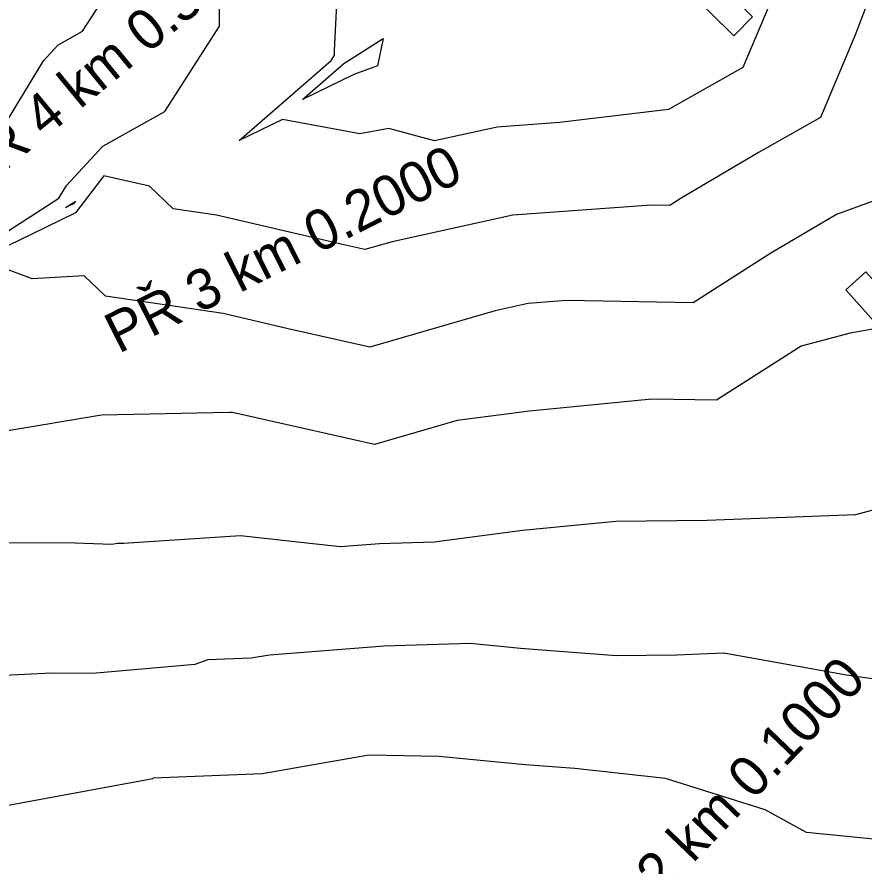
# Model space of a CAD drawing. Extents: x -549394 to -546608, y -1037055 to -1033629.
# Drawn here: x -548001.4 to -547811.8, y -1034975.5 to -1034785.5 of the extents above; entities that cross this region are included whole.
import ezdxf

# ---------------------------------------------------------------- set-up
doc = ezdxf.new("R2010")
doc.units = 0
for name, color, linetype in [('hlavni_vrst', 7, 'Continuous'), ('norm_vrst', 7, 'Continuous'), ('x_popis_oblouky_C21', 7, 'Continuous'), ('x_popis_pricne_rezy_C21', 7, 'Continuous')]:
    doc.layers.add(name, color=color, linetype=linetype)

msp = doc.modelspace()

# ---------------------------------------------------------------- linework, layer by layer
at = {"layer": 'hlavni_vrst'}
for p, q in [((-547930.28, -1034793.03), (-547929.09, -1034769.59)), ((-547831.37, -1034778.88), (-547838.89, -1034796.79)), ((-547930.29, -1034794.03), (-547930.28, -1034793.03)), ((-547931.04, -1034795.2), (-547930.29, -1034794.03)), ((-547951.64, -1034813.16), (-547931.04, -1034795.2)), ((-547838.89, -1034796.79), (-547855.54, -1034806.2)), ((-547855.54, -1034806.2), (-547879.97, -1034809.11)), ((-547941.92, -1034808.45), (-547951.64, -1034813.16)), ((-547924.61, -1034811.63), (-547941.92, -1034808.45)), ((-547893.86, -1034810.13), (-547907.91, -1034813.21)), ((-547879.97, -1034809.11), (-547893.86, -1034810.13)), ((-547918.17, -1034810.42), (-547924.61, -1034811.63)), ((-547907.91, -1034813.21), (-547918.17, -1034810.42)), ((-547990.49, -1034828.14), (-547988.82, -1034827.07)), ((-547988.74, -1034827.29), (-547990.49, -1034828.14)), ((-547988.82, -1034827.07), (-547988.28, -1034826.69)), ((-547988.28, -1034826.69), (-547988.74, -1034827.29)), ((-547899.96, -1034925.75), (-547919.16, -1034926.31)), ((-547888.65, -1034926.85), (-547899.96, -1034925.75)), ((-547919.16, -1034926.31), (-547944.85, -1034928.3)), ((-547867.23, -1034928.45), (-547888.65, -1034926.85)), ((-547843.16, -1034927.89), (-547853.64, -1034928.29)), ((-547815.68, -1034932.82), (-547843.16, -1034927.89)), ((-547958.65, -1034929.4), (-547961.54, -1034930.44)), ((-547948.95, -1034929.01), (-547958.65, -1034929.4)), ((-547944.85, -1034928.3), (-547948.95, -1034929.01)), ((-547853.64, -1034928.29), (-547867.23, -1034928.45)), ((-547961.54, -1034930.44), (-547984.49, -1034932.45)), ((-547993.65, -1034932.39), (-548021.3, -1034933.65)), ((-547984.49, -1034932.45), (-547993.65, -1034932.39)), ((-547782.76, -1034937.38), (-547815.68, -1034932.82))]:
    msp.add_line(p, q, dxfattribs=at)
at = {"layer": 'norm_vrst'}
for p, q in [((-547956.05, -1034787.56), (-547955.75, -1034744.77)), ((-547807.11, -1034772.14), (-547813.87, -1034789.74)), ((-547986.68, -1034788.68), (-547981.82, -1034781.1)), ((-547992.19, -1034791.77), (-547986.68, -1034788.68)), ((-547968.28, -1034806.63), (-547956.05, -1034787.56)), ((-547928.21, -1034795.9), (-547919.44, -1034790.29)), ((-547919.44, -1034790.29), (-547920.65, -1034796.4)), ((-547813.87, -1034789.74), (-547821.53, -1034807.96)), ((-547995.42, -1034795.27), (-547992.19, -1034791.77)), ((-548004.18, -1034809.72), (-547995.42, -1034795.27)), ((-547937.43, -1034803.93), (-547928.21, -1034795.9)), ((-547920.65, -1034796.4), (-547925.94, -1034798.36)), ((-547925.94, -1034798.36), (-547937.43, -1034803.93)), ((-547982.15, -1034814.41), (-547968.28, -1034806.63)), ((-547821.53, -1034807.96), (-547835.25, -1034815.72)), ((-547990.28, -1034823.21), (-547982.15, -1034814.41)), ((-547835.25, -1034815.72), (-547852.72, -1034826.06)), ((-547981.95, -1034821.06), (-547988.27, -1034829.32)), ((-547971.69, -1034823.37), (-547981.95, -1034821.06)), ((-547991.97, -1034826.01), (-547990.28, -1034823.21)), ((-547966.4, -1034828.41), (-547971.69, -1034823.37)), ((-547798.33, -1034822.53), (-547817.93, -1034829.7)), ((-548007.41, -1034835.99), (-547991.97, -1034826.01)), ((-547852.72, -1034826.06), (-547855.25, -1034827.67)), ((-547956.72, -1034829.83), (-547966.4, -1034828.41)), ((-547859.37, -1034827.6), (-547890.4, -1034829.87)), ((-547855.25, -1034827.67), (-547859.37, -1034827.6)), ((-547988.27, -1034829.32), (-547998.17, -1034834.14)), ((-547927.5, -1034836.66), (-547956.72, -1034829.83)), ((-547890.4, -1034829.87), (-547917.38, -1034835.78)), ((-547817.93, -1034829.7), (-547832.61, -1034838.39)), ((-547998.17, -1034834.14), (-548005.82, -1034837.88)), ((-547923.51, -1034837.56), (-547927.5, -1034836.66)), ((-547917.38, -1034835.78), (-547923.51, -1034837.56)), ((-547832.61, -1034838.39), (-547850.01, -1034849.47)), ((-547997.95, -1034844.08), (-548005.18, -1034841.41)), ((-547986.35, -1034843.44), (-547997.95, -1034844.08)), ((-547981.54, -1034848.01), (-547986.35, -1034843.44)), ((-547955.18, -1034851.89), (-547981.54, -1034848.01)), ((-547886.94, -1034849.61), (-547894.37, -1034851.24)), ((-547878.4, -1034848.98), (-547886.94, -1034849.61)), ((-547850.01, -1034849.47), (-547878.4, -1034848.98)), ((-547940.64, -1034855.29), (-547955.18, -1034851.89)), ((-547894.37, -1034851.24), (-547922.42, -1034859.39)), ((-547922.42, -1034859.39), (-547940.64, -1034855.29)), ((-547806.07, -1034854.69), (-547814.85, -1034856.23)), ((-547814.85, -1034856.23), (-547825.82, -1034859.2)), ((-547825.82, -1034859.2), (-547844.76, -1034871.27)), ((-547859.29, -1034871.02), (-547886.63, -1034873.7)), ((-547844.76, -1034871.27), (-547859.29, -1034871.02)), ((-547982.46, -1034874.58), (-548003.88, -1034878.17)), ((-547953.89, -1034874.01), (-547982.46, -1034874.58)), ((-547953.63, -1034874), (-547953.89, -1034874.01)), ((-547953.14, -1034874.05), (-547953.63, -1034874)), ((-547921.32, -1034881.21), (-547953.14, -1034874.05)), ((-547886.63, -1034873.7), (-547902.85, -1034875.84)), ((-547902.85, -1034875.84), (-547921.32, -1034881.21)), ((-547805.97, -1034894.81), (-547813.7, -1034896.91)), ((-547813.7, -1034896.91), (-547846.86, -1034898.15)), ((-547867.33, -1034898.4), (-547888.25, -1034900.45)), ((-547846.86, -1034898.15), (-547867.33, -1034898.4)), ((-547888.25, -1034900.45), (-547908.02, -1034903.06)), ((-547988.35, -1034903.27), (-548022.77, -1034903.03)), ((-547980.15, -1034903.57), (-547988.35, -1034903.27)), ((-547978.88, -1034903.35), (-547980.15, -1034903.57)), ((-547977.52, -1034903.32), (-547978.88, -1034903.35)), ((-547951.3, -1034901.62), (-547977.52, -1034903.32)), ((-547929.01, -1034904.1), (-547951.3, -1034901.62)), ((-547908.02, -1034903.06), (-547920.23, -1034903.42)), ((-547920.23, -1034903.42), (-547929.01, -1034904.1)), ((-547922.58, -1034950.69), (-547946.52, -1034954.85)), ((-547906.92, -1034950.97), (-547922.58, -1034950.69)), ((-547887.61, -1034952.84), (-547906.92, -1034950.97)), ((-547876.5, -1034953.67), (-547887.61, -1034952.84)), ((-547856.21, -1034955.96), (-547876.5, -1034953.67)), ((-547970.95, -1034956.03), (-548012.58, -1034963.69)), ((-547970.95, -1034956.03), (-547970.85, -1034955.84)), ((-547946.52, -1034954.85), (-547970.85, -1034955.84)), ((-547833.93, -1034962.94), (-547856.21, -1034955.96)), ((-547824.62, -1034968.04), (-547833.93, -1034962.94)), ((-547797.03, -1034970.72), (-547824.62, -1034968.04))]:
    msp.add_line(p, q, dxfattribs=at)
at = {"layer": 'x_popis_oblouky_C21'}
for points in [[(-547840.95, -1034789.73), (-547862.28, -1034768.63), (-547858.06, -1034764.37), (-547836.73, -1034785.46)], [(-547795.85, -1034868.91), (-547815.85, -1034846.56), (-547811.38, -1034842.56), (-547791.38, -1034864.91)]]:
    msp.add_lwpolyline(points, close=True, dxfattribs=at)

# ---------------------------------------------------------------- texts
at = {"layer": 'x_popis_pricne_rezy_C21'}
for s, rotation, p in [('PŘ 4 km 0.3000', 39.4445, (-548010.7, -1034825.52)), ('PŘ 3 km 0.2000', 26.7249, (-547978.63, -1034860.95)), ('PŘ 2 km 0.1000', 46.2217, (-547871.04, -1034996.92))]:
    msp.add_text(s, height=9.0627, rotation=rotation, dxfattribs=at).set_placement(p)

doc.saveas('drawing.dxf')
